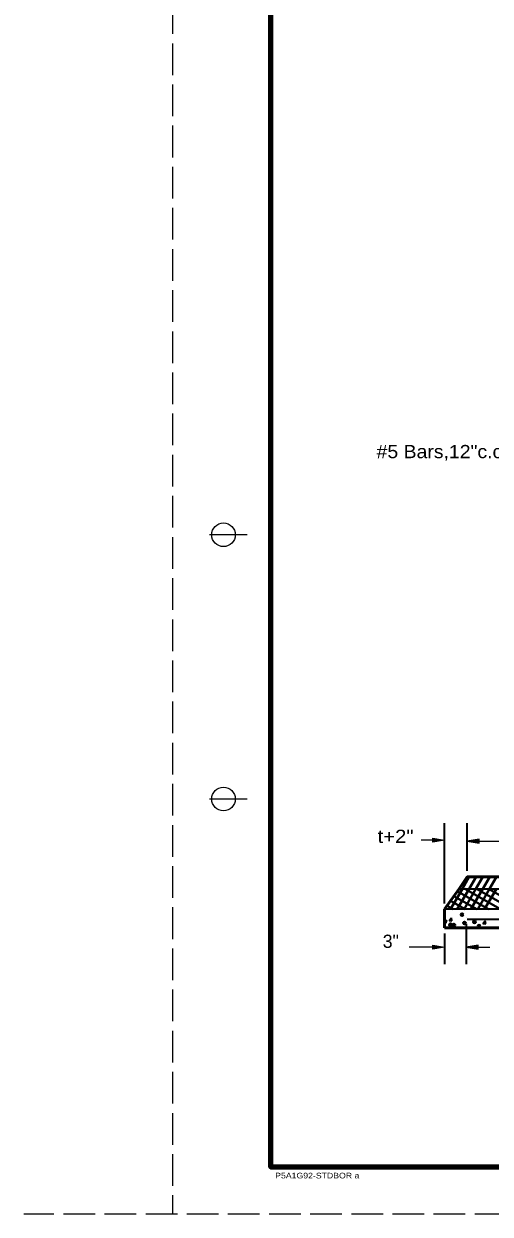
# Model space of a CAD drawing. Extents: x 36.4 to 71.7, y 0.5 to 22.5.
# Drawn here: x 36.4 to 41.35, y 0.48 to 13.09 of the extents above; entities that cross this region are included whole.
import ezdxf

# ---------------------------------------------------------------- set-up
doc = ezdxf.new("R2010")
doc.units = 0
doc.header["$LTSCALE"] = 0.056
doc.header["$PDMODE"] = 32
doc.header["$PDSIZE"] = 0.028
doc.linetypes.add('LONG_DASHED', pattern=[7.5, 6, -1.5])
for name, color, linetype, lineweight in [('1', 7, 'Continuous', 40), ('3', 7, 'Continuous', 13), ('6', 7, 'Continuous', 13)]:
    doc.layers.add(name, color=color, linetype=linetype, lineweight=lineweight)

msp = doc.modelspace()

# ---------------------------------------------------------------- hatches: boundary and pattern name
at = {"layer": '1'}
for points in [[(41.22775, 4.41017), (41.22775, 4.45183), (41.10275, 4.431), (41.10275, 4.431)], [(40.73717, 3.28608), (40.73717, 3.32775), (40.86217, 3.30692), (40.86217, 3.30692)], [(41.21683, 3.28608), (41.21683, 3.32775), (41.09183, 3.30692), (41.09183, 3.30692)]]:
    msp.add_hatch(color=256, dxfattribs=at).paths.add_polyline_path(points)
at = {"layer": '3'}
msp.add_hatch(color=256, dxfattribs=at).paths.add_polyline_path([(40.73717, 4.42158), (40.73717, 4.46333), (40.86217, 4.4425), (40.86217, 4.4425)])

# ---------------------------------------------------------------- linework, layer by layer
at = {"layer": '1', "linetype": 'LONG_DASHED', "lineweight": 25}
for p, q in [((37.97642, 22.47742), (37.97642, 0.47742)), ((71.60142, 0.47742), (36.40142, 0.47742))]:
    msp.add_line(p, q, dxfattribs=at)
at = {"layer": '1', "lineweight": 158}
msp.add_line((39.01808, 21.97742), (39.01808, 0.97742), dxfattribs=at)
at = {"layer": '1', "lineweight": 13}
for p, q in [((38.76808, 7.67742), (38.36808, 7.67742)), ((38.76808, 4.87742), (38.36808, 4.87742)), ((41.10275, 4.115), (41.10275, 4.611))]:
    msp.add_line(p, q, dxfattribs=at)
at = {"layer": '1', "lineweight": 25}
for p, q in [((41.22775, 4.431), (47.54917, 4.431)), ((40.61217, 3.30692), (40.48717, 3.30692)), ((40.73717, 3.30692), (40.61217, 3.30692)), ((41.21683, 3.30692), (41.34183, 3.30692))]:
    msp.add_line(p, q, dxfattribs=at)
at = {"layer": '1'}
for p, q in [((41.05025, 3.92633), (41.12308, 4.0525)), ((41.12242, 3.92633), (41.19525, 4.0525)), ((41.19458, 3.92633), (41.26742, 4.0525)), ((41.26675, 3.92633), (41.33958, 4.0525)), ((41.33892, 3.92633), (41.41175, 4.0525)), ((40.92442, 3.70842), (41.05025, 3.92633)), ((40.99658, 3.70842), (41.12242, 3.92633)), ((41.06875, 3.70842), (41.19458, 3.92633)), ((41.07567, 3.92633), (41.45317, 3.70842)), ((41.14092, 3.70842), (41.26675, 3.92633)), ((41.20067, 3.92633), (41.57817, 3.70842)), ((41.21308, 3.70842), (41.33892, 3.92633)), ((41.28525, 3.70842), (41.41108, 3.92633)), ((41.32567, 3.92633), (41.70317, 3.70842)), ((40.9245, 3.79708), (41.07817, 3.70842)), ((40.96058, 3.84842), (41.20317, 3.70842)), ((40.99667, 3.89983), (41.32817, 3.70842)), ((40.88842, 3.74575), (40.95317, 3.70842))]:
    msp.add_line(p, q, dxfattribs=at)
at = {"layer": '1', "lineweight": 53}
for q in [(41.01525, 3.92633), (40.86217, 3.51342)]:
    msp.add_line((40.86217, 3.70842), q, dxfattribs=at)
at = {"layer": '1', "lineweight": 35}
for p, q in [((41.01525, 3.92633), (47.77258, 3.92633)), ((47.9475, 3.70842), (40.86217, 3.70842)), ((40.86217, 3.58292), (40.88675, 3.59233)), ((40.86217, 3.57183), (40.87667, 3.56208)), ((40.87667, 3.56208), (40.88675, 3.59233)), ((40.90975, 3.58892), (40.93383, 3.61758)), ((40.90975, 3.58892), (40.93967, 3.58625)), ((40.93967, 3.58625), (40.93383, 3.61758)), ((41.09183, 3.55417), (41.09183, 3.12692)), ((41.10275, 3.60517), (47.73975, 3.60517)), ((41.26842, 3.5575), (41.2925, 3.58625)), ((41.26842, 3.5575), (41.29825, 3.55492)), ((41.29825, 3.55492), (41.2925, 3.58625)), ((40.86217, 3.45092), (40.86217, 3.12692))]:
    msp.add_line(p, q, dxfattribs=at)
at = {"layer": '1', "lineweight": 158}
msp.add_lwpolyline([(71.51808, 21.97742), (71.51808, 0.97742), (39.01808, 0.97742)], dxfattribs=at)
at = {"layer": '1', "lineweight": 13}
for points in [[(41.22775, 4.41017), (41.22775, 4.45183), (41.10275, 4.431), (41.10275, 4.431)], [(40.73717, 3.28608), (40.73717, 3.32775), (40.86217, 3.30692), (40.86217, 3.30692)], [(41.21683, 3.28608), (41.21683, 3.32775), (41.09183, 3.30692), (41.09183, 3.30692)]]:
    msp.add_lwpolyline(points, close=True, dxfattribs=at)
at = {"layer": '1', "lineweight": 53}
for points in [[(41.01525, 3.92633), (41.10275, 4.0525), (47.67417, 4.0525), (47.77258, 3.92633)], [(40.86217, 3.51342), (47.9475, 3.51342), (47.9475, 3.70842)]]:
    msp.add_lwpolyline(points, dxfattribs=at)
at = {"layer": '1', "lineweight": 13}
for centre in [(38.51808, 7.67742), (38.51808, 4.87742)]:
    msp.add_circle(centre, 0.125, dxfattribs=at)
at = {"layer": '1'}
for p in [(41.04683, 3.65175), (40.92542, 3.54475), (40.96008, 3.54108), (41.07292, 3.56333), (41.178, 3.57675), (41.227, 3.52983), (39.01808, 0.97742)]:
    msp.add_point(p, dxfattribs=at)
at = {"layer": '3', "lineweight": 35}
for p, q in [((40.86217, 3.77092), (40.86217, 4.6225)), ((41.10275, 4.115), (41.10275, 4.6225))]:
    msp.add_line(p, q, dxfattribs=at)
at = {"layer": '3', "lineweight": 25}
msp.add_line((40.73717, 4.4425), (40.61217, 4.4425), dxfattribs=at)
at = {"layer": '3'}
msp.add_line((41.10275, 4.4425), (41.10283, 4.4425), dxfattribs=at)
msp.add_lwpolyline([(40.73717, 4.42158), (40.73717, 4.46333), (40.86217, 4.4425), (40.86217, 4.4425)], close=True, dxfattribs=at)
at = {"layer": '6'}
for p, q in [((41.10275, 4.0525), (41.10283, 4.0525)), ((41.10275, 4.0525), (41.10283, 4.0525)), ((40.86217, 3.70842), (40.86225, 3.70842)), ((41.09183, 3.61667), (41.09192, 3.61667)), ((40.86217, 3.51342), (40.86225, 3.51342)), ((40.86217, 3.30692), (40.86225, 3.30692))]:
    msp.add_line(p, q, dxfattribs=at)

# ---------------------------------------------------------------- texts
at = {"layer": '1', "width": 1.15}
msp.add_text('P5A1G92-STDBOR a', height=0.06, dxfattribs=at).set_placement((39.06608, 0.85642))
at = {"layer": '3'}
for s, width, p in [('#5 Bars,12"c.c.,4\'long', 1.1, (40.141, 8.48925)), ('t+2"', 1.15, (40.15108, 4.412))]:
    msp.add_text(s, height=0.14, dxfattribs=dict(at, width=width)).set_placement(p)
msp.add_text('3"', height=0.14, dxfattribs=at).set_placement((40.2065, 3.29975))

doc.saveas('drawing.dxf')
